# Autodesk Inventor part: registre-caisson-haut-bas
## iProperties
Author: chr
Created: 2001-06
Part Number: registre-caisson-haut-bas
Material: Par défaut
Document SubType Name: Tôlerie
Designer: chr
Control State: 0
Master: False
Checked Out: False
PropertySet Name: Design Tracking Control
Shininess: 21.0
PropertySet Name: _Private Model Information
Length Units: 11269
Angle Units: 11286
Time Units: 11279
Mass Units: 11290
Length Display Precision: 3
Angle Display Precision: 2
Compacted: False
Density: 0.0
Volumn: 0.0
Area: 0.0
PropertySet Name: Model Information
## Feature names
1. Perçage1 [Hole]
2. Plaque1
3. Plaque2
4. Pli1
5. Plaque3
6. Pli2
7. Plaque4
8. Pli3
9. Plaque5
10. Pli4
11. Plaque6
12. Pli5
13. Plaque7
14. Pli6
